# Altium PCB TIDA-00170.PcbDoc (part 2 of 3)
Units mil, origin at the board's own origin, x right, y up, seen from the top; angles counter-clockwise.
Board outline 3780 x 2000 mil, 4 copper layers (Top Layer, L2_GND-PLANE, L3_PWR-PLANE, Bottom Layer), stack 90 mil thick; 275 components, 132 nets, 768 pads, 262 vias.
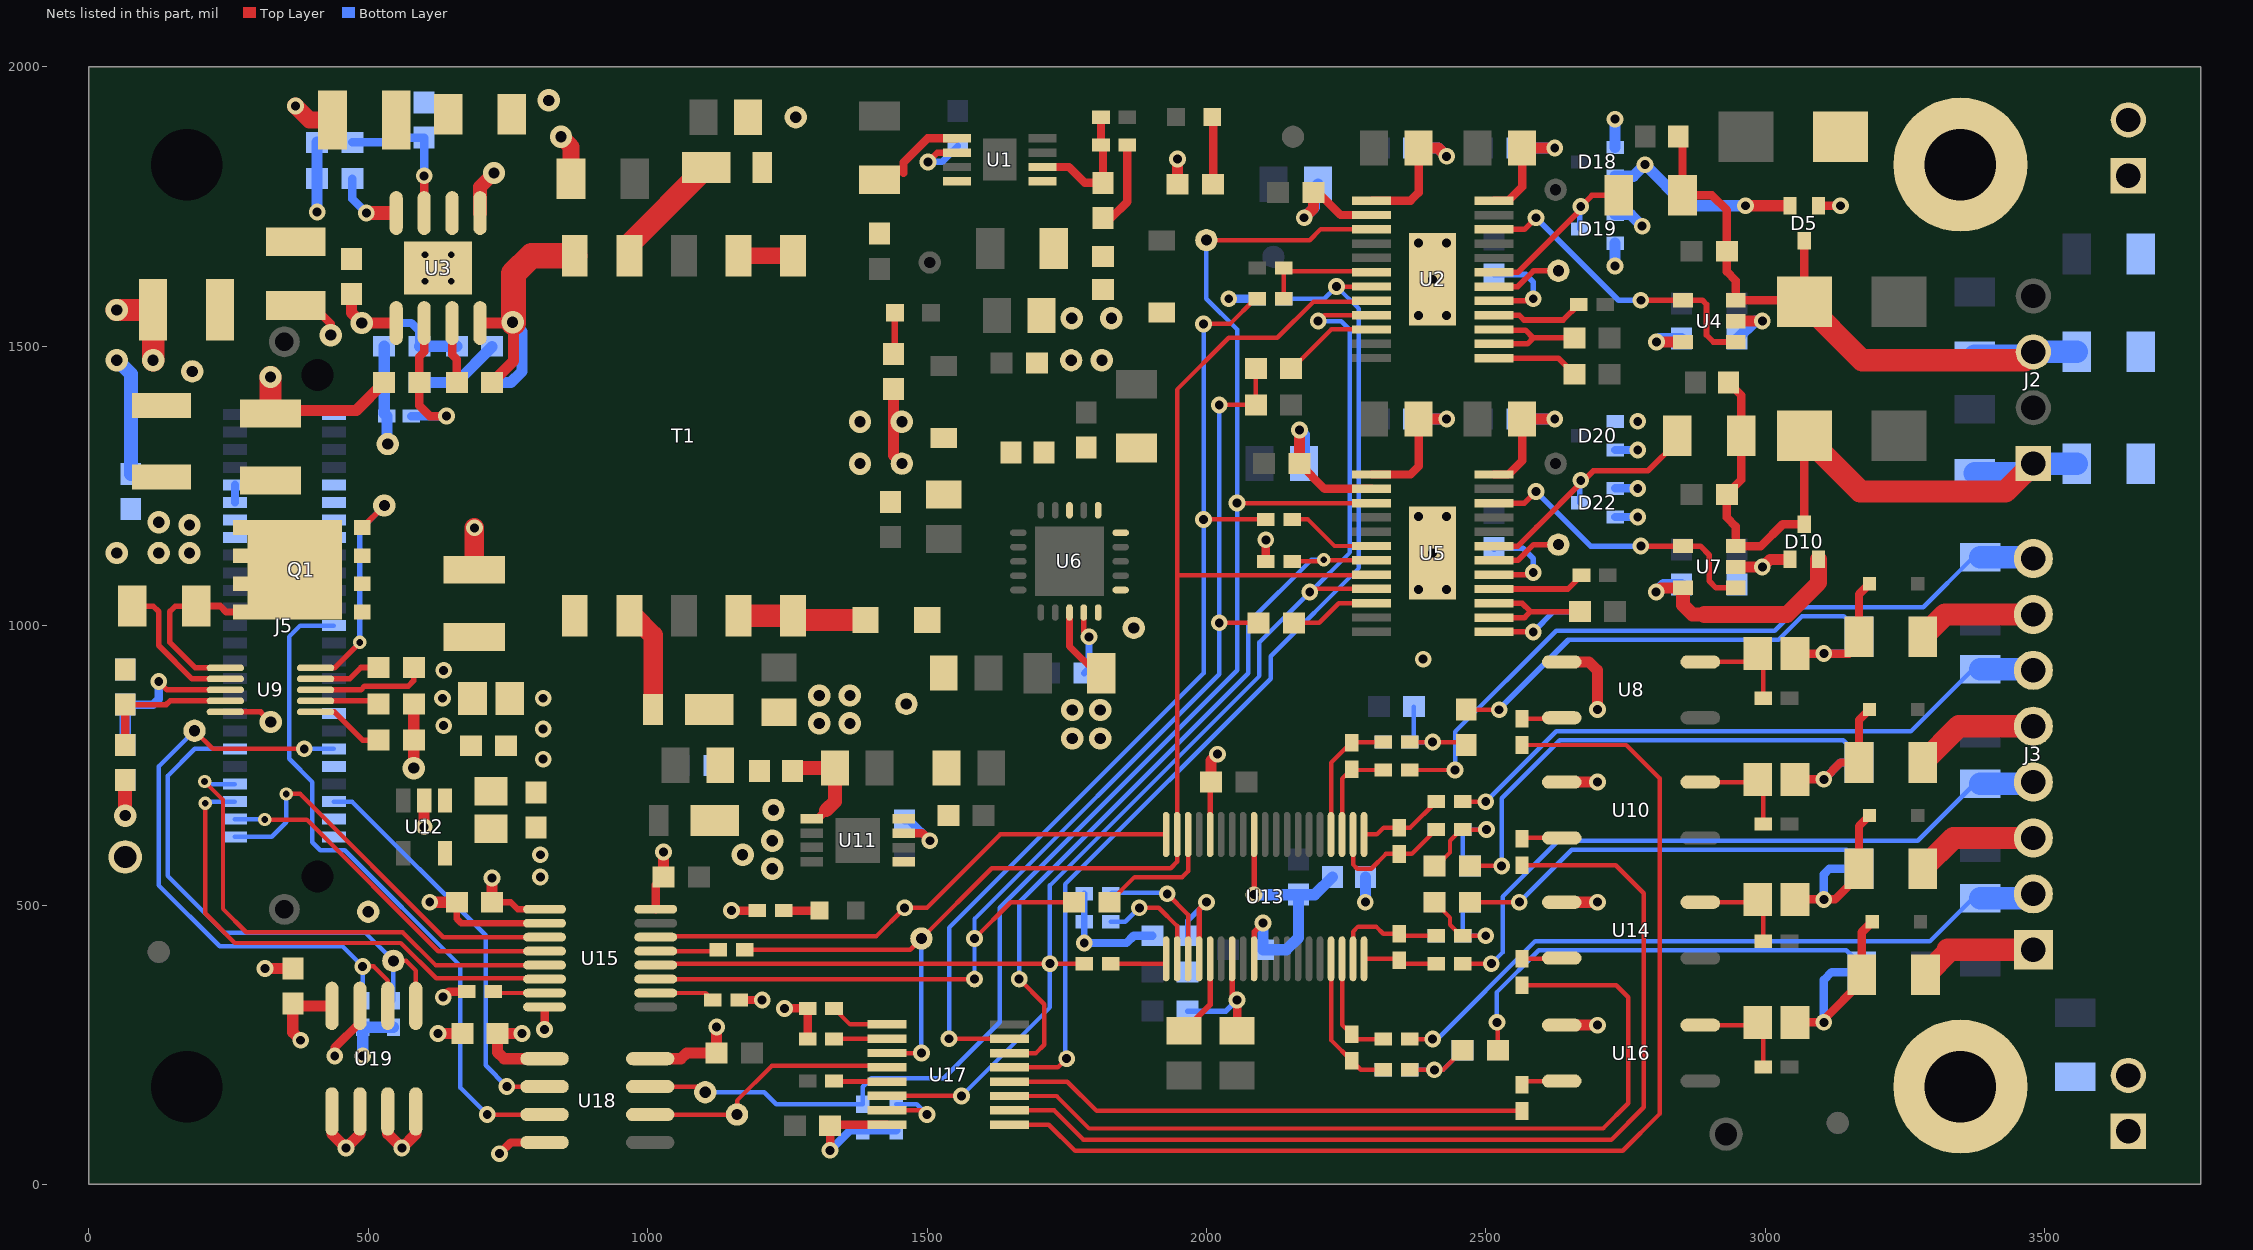
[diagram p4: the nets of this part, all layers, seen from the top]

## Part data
C1 C15 C22: "CAP, CERM, 2.2uF, 100V, +/-10%, X7R, 1210"
C2: "CAP, CERM, 0.47uF, 100V, +/-10%, X7R, 1206"
C3 C34 C35: "CAP, CERM, 2.2uF, 25V, +/-10%, X7R, 0805"
C4 C33: "CAP, CERM, 4.7uF, 50V, +/-10%, X7R, 1206"
C5 C6 C16 C23 C24 C28 C43 C66 C78: "CAP, CERM, 4.7uF, 50V, +/-10%, X5R, 0805"
C7 C67 C68 C71 C74 C77 C93: "CAP, CERM, 1000pF, 2KV 10% X7R 1206"
C8 C21 C63: "CAP, CERM, 0.01uF, 100V, +/-5%, X7R, 0603"
C9 C11 C14 C17 C18 C25 C27 C29 C30 C32 C40 C46 C47 C48 C51 C52 C55 C58 C60 C62 C64 C65 C69 C70 C75 C76 C80 C81: "CAP, CERM, 0.1uF, 50V, +/-10%, X7R, 0603"
C10 C26: "CAP, CERM, 3900pF, 50V, +/-10%, X7R, 0603"
C12 C19: "CAP, CERM, 10uF, 25V, +/-10%, X7R, 1206"
C13: "CAP, CERM, 10uF, 50V, +/-10%, X7R, 1210"
C20: "CAP, CERM, 1uF, 50V, +/-10%, X5R, 0603"
C31: "CAP, CERM, 10uF, 35V, +/-20%, X7R, 1210"
C36: "CAP, CERM, 1uF, 50V, +/-10%, X7R, 0805"
C37 C49 C54 C61: "CAP, CERM, 1000pF, 50V, +/-20%, X7R, 0402"
C38: "CAP, CERM, 0.47uF, 50V, 10%, X5R, 0603"
C39 C50 C53 C59: "CAP, CERM, 0.01uF, 50V, +/-10%, X7R, 0402"
C41 C42: "CAP, CERM, 22uF, 16V, +/-20%, X5R, 0805"
C44: "CAP, CERM, 10uF, 25V, +/-20%, X5R, 0603"
C45 C56: "CAP, CERM, 10uF, 16V, +/-20%, X5R, 0805"
C57: "CAP, CERM, 22uF, 16V, +/-10%, X5R, 0805"
C72: "CAP, CERM, 0.1uF, 100V, +/-10%, X7R, 0603"
C73: "CAP, CERM, 3300pF, 100V, +/-5%, X7R, 0603"
C79: "CAP, CERM, 1000pF, 100V, +/-20%, X7R, 0603"
C82 C85 C87 C92: "CAP, CERM, 0.027uF, 50V, +/-5%, C0G/NP0, 1206"
C83: "CAP, CERM, 1uF, 25V, +/-10%, X7R, 0603"
C84 C89 C90 C95: "CAP, CERM, 2700pF, 100V, +/-5%, X7R, 0603"
C86: "CAP, CERM, 1000pF, 100V, +/-5%, X7R, 0603"
C88 C91: "CAP, CERM, 10uF, 16V, +/-20%, X5R, 0603"
C94: "CAP, CERM, 1uF, 16V, +/-10%, X7R, 0603"
D1 D6 D16: "LED SmartLED Green 570NM"
D2 D7 D9: "TVS 18 VOLT 600 WATT BI-DIR SMB"
D3 D13: "Diode, Schottky, 200V, 1A, PowerDI123"
D4 D8: "Diode, Zener, 18V, 1W, SOD-123"
D5 D10 D18 D19 D20 D22: library part BAV99WT1G, "Diode, P-N, 70V, 0.2A, SOT-323"
D11 D14 D15 D17: library part CDSOD323-T15SC, "Diode, TVS, ARRAY, 19V, SOD323"
D12: "Diode, Schottky, 60V, 1A, SOD-123F"
D21: "Diode, Schottky, 45V, 0.1A, SOD-523"
D23: "DIODE ZENER 5.9V 1W PMDS"
FB1 FB2: library part MMZ1608Y102B, "FERRITE CHIP 1000 OHM 300MA 0603"
FB3 L1 L3 L4: library part MMZ1608B102C, "FERRITE CHIP 1000 OHM 300MA 0603"
FID1 FID2 FID3 FID4 FID5 FID6: library part Fiducial40_0
H1 H2: "Machine Screw, Round, #4-40 x 1/4, Nylon, Philips panhead"
J1 J4: "Terminal Block, 2x1, 2.54mm, TH"
J2: "Receptacle, 100mil, 4X1 TH"
J3: "Terminal Block, 8x1, 2.54 mm, TH"
J5: "Receptacle, 0.8mm, 25x2, SMT"
L2: library part IND_ELJEA_SERIES, "Inductor, Chip, ±10%"
LBL1: library part THT-14-423-10, "Thermal Transfer Printable Labels, 0.650\" W x 0.200\" H - 10,000 per roll"
Logo1: library part TI_Logo, "Texas Instrument Corporate Signature"
MH1 MH2: library part "MH 3_0.5MM", "Mountin hole, NPTH Drill 3.2mm"
Q1: "MOSFET, N-CH, 60V, 50A, SON 5x6mm"
R1: library part CRCW04029K31FKED, "RES, 9.42k ohm, 1%, 0.063W, 0402"
R2: "RES, 110k ohm, 1%, 0.063W, 0402"
R3 R13: "RES, 10 ohm, 5%, 0.25W, 1206"
R4 R9: "RES, 4.7k ohm, 5%, 0.1W, 0603"
R5: "RES, 27.0k ohm, 1%, 0.1W, 0603"
R6 R7 R8 R14 R15 R28 R33 R41 R42 R54: "RES, 0 ohm, 5%, 0.063W, 0402"
R10 R19 R38: "RES, 10.0 ohm, 1%, 0.1W, 0603"
R11 R18: "RES, 15k ohm, 1/10W 0.1% 0603"
R12 R25 R36 R39 R53: "RES, 1.00k ohm, 1%, 0.1W, 0603"
R16 R47 R48 R49 R51 R55 R60 R79 R80: "RES, 10k ohm, 5%, 0.063W, 0402"
R17: "RES, 0.02 ohm, 1%, 1W, 1206"
R20 R29 R35 R44: "RES 100 OHM .4W 1% 0204 MELF"
R21 R30 R37 R50: "RES, 200 ohm, 0.1%, 0.125W, 0805"
R22: "RES, 10k ohm, 5%, 0.1W, 0603"
R23: "RES, 95.3k ohm, 1%, 0.1W, 0603"
R24: "RES, 56.0k ohm, 0.1%, 0.1W, 0603"
R26 R34 R43 R56: "RES, 680 ohm, 5%, 0.063W, 0402"
R27: "RES, 7.15k ohm, 1%, 0.1W, 0603"
R31 R32 R46 R52: "RES, 1.10k ohm, 1%, 0.063W, 0402"
R40: "RES, 1.2k ohm, 5%, 0.063W, 0402"
R45: "RES, 49.9 ohm, 1%, 0.063W, 0402"
R57: "RES, 4.87k ohm, 1%, 0.1W, 0603"
R58: "RES, 60.4k ohm, 0.1%, 0.1W, 0603"
R59: "RES, 91.0k ohm, 1%, 0.1W, 0603"
R61: "RES, 189k ohm, 0.1%, 0.1W, 0603"
R62: "RES, 56.2k ohm, 0.1%, 0.1W, 0603"
R63 R64 R68 R70: "RES 0.0 OHM .5W JUMP 1206 SMD"
R65: "RES, 71.5k ohm, 1%, 0.1W, 0603"
R66: "RES, 14.3k ohm, 1%, 0.1W, 0603"
R67 R69 R74 R78: "RES, 10.0Meg ohm, 1%, 0.063W, 0402"
R71 R72: "RES, 47k ohm, 5%, 0.063W, 0402"
R73 R75: "RES, 47.0k ohm, 0.1%, 0.1W, 0603"
R76 R77: "RES, 1.5k ohm, 5%, 0.063W, 0402"
T1: library part 750313995, "Transformer, 50uH, SMT"
TP1 TP4 TP7 TP8 TP13 TP14 TP18 TP19 TP23 TP26 TP27 TP28: library part TP-040_RND, "Test Point 40mil pad 20mil drill"
TP2 TP3 TP5 TP6 TP9 TP10 TP11 TP12 TP15 TP16 TP17 TP20 TP21 TP22 TP24 TP25: "Test Point 40mil pad 20mil drill"
U1: "-36V, -200mA, Ultralow-Noise, Negative Linear Regulator"
U2 U5: "1-Channel, 16-Bit, Programmable Current/Voltage Output DAC for 4-20mA Current Loop Applications"
U3: "100V, 600mA Constant On-Time Synchronous Buck Regulator, DDA0008B"
U4 U7: "Precision, Low Noise, Rail-to-Rail Output, 36V Zero-Drift Operational Amplifier"
U6: "36-V, 1-A, 4.17-µVRMS, RF LDO Voltage Regulator, RGW0020A"
U8 U10 U14 U16: "PHOTORELAY MOSFET 1A 4-SOP"
U9: "Positive High Voltage Hot Swap / Inrush Current Controller with Power Limiting, 10-pin MSOP, Pb-Free"
U11: library part TPS7A16XXDGN, "IC, 60-V, 6-A IQ, 100-mA, LDO Voltage Regulator with Enable and Power-Good Functions"
U12: "IC REG LDO 3.3V 0.15A SOT23-5"
U13: "16 bit 400KSPS 8 Channel SAR ADC"
U15: "4242-VPK Small-Footprint and Low-Power Quad Channels Digital Isolators, DBQ0016A"
U17: "IC, 8-Bit Shift Registers With 3-State Output Registers"
U18: "Low-Power Bidirectional I2C Isolators, D0008A"
U19: "IC, EEPROM, 2KBIT, 1MHZ, SOIC-8"
ZZ1: library part AssemblyNoteLabel
ZZ2 ZZ3 ZZ4: library part AssemblyNote

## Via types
v1: diameter 30, hole 16, Top Layer to Bottom Layer, tented both sides, 197 vias
v2: diameter 40, hole 20, Top Layer to Bottom Layer, tented both sides, 46 vias
v3: diameter 20, hole 8, Top Layer to Bottom Layer, tented both sides, 9 vias
v4: diameter 24, hole 12, Top Layer to Bottom Layer, tented both sides, 6 vias
v5: diameter 25.98, hole 12, Top Layer to Bottom Layer, tented both sides, 4 vias

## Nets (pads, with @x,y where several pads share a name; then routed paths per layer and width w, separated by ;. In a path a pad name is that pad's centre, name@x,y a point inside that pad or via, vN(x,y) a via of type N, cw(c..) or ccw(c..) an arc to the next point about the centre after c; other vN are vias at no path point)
9.3V_NON_ISO: C31.1 C36.1 C40.1 C73.2 D21.2 R61.2 T1.10 TP8.1 U12.1 | length 177.7
  Bottom Layer w20: R61.2@528.5,1500 C73.2@528.5,1435 528.5,1379.84 D21.2@533.35,1375 533.35,1326.65 TP8.1@535,1325
  other v1: 635,821 633,870 635,920
+3.3V_NON_ISO: C45.1 C46.1 C52.2 C55.2 C58.2 R47.1 R76.1 R77.1 TP19.1 U12.5 U15.1 U18.1 U19.8 | length 604.6
  Top Layer w12: C52.2@721.5,505 755,505 767.5,492.5 U15.1@815.59,492.5
  Top Layer w15: v1(634,335) 644,345 R47.1@676.38,345
  Top Layer w20: v1(379,258) 365,272 C55.2@365,323.5 369.02,319.49 U19.8@435,319.49 ; C52.2@721.5,505 v1(721.5,548.5) ; v1(775.18,270) C58.2@731.5,270 731.5,236.5 743,225 U18.1@815.51,225
  Bottom Layer w20: v1(490,230) R77.1@490,281.38 R76.1@545,281.38
  other v1: 808,550 808,590
+5V_ISO: C9.2 C27.2 C43.1 C44.1 C48.2 C51.1 C60.1 C62.2 C66.2 C78.1 D23.1 FB3.1 L4.2 R16.2 R40.1 R48.2 R49.1 R51.1 R60.2 R71.1 R72.1 R73.1 R79.2 R80.2 TP16.1 U2.2 U5.2 U8.1 U10.1 U13.34 U14.1 U15.16 U16.1 U17.16 U18.8 | length 2083.8
  Top Layer w10: C44.1@1998.5,720 C44.1@2003.5,715 ; U13.34@2006.57,626.22 C44.1@2006.57,711.93
  Top Layer w15: U15.16@1014.41,492.5 1014.41,535.91 C51.1@1028.5,550 ; v1(1150,490) R40.1@1196.38,490 ; R48.2@1168.62,330 v1@1210,330 ; v1(1245,315) R49.1@1286.38,315 R51.1@1286.38,260 ; v1(1326.5,61) C62.2@1326.5,105 ; C62.2@1328.5,107 U17.16@1428.3,107 ; R16.2@2106.38,1115 v1(2106.38,1153.62) ; C27.2@2166.5,1290 2211.6,1244.9 U5.2@2295.7,1244.9 ; C9.2@2191.5,1775 2199.98,1775 2240.08,1734.9 U2.2@2295.7,1734.9
  Top Layer w20: U18.8@1004.49,225 1060,225 1070,235 C60.1@1123.5,235 v1(1123.5,281.5) ; C51.1@1028.5,550 v1(1028.5,595) ; C44.1@2008.5,720 2008.5,758.5 v1(2020,770) ; C27.2@2166.5,1290 v1(2166.5,1350) ; v1(2175,1730) 2191.5,1746.5 C9.2@2191.5,1775 ; U16.1@2635.98,285 v1(2700,285) ; U14.1@2635.98,505 v1(2700,505) ; U10.1@2635.98,720 v1(2700,720) ; U8.1@2635.98,935 2685,935 2700,920 v1(2700,850)
  Bottom Layer w12: v1(1781.38,432) R72.1@1781.38,470 R71.1@1781.38,520
  Bottom Layer w15: v1(1326.5,61) 1361.87,96.38 R80.2@1385,96.38 R79.2@1445,96.38 ; v1(1781.38,432) 1857,432 1870,445 R73.1@1903.5,445 ; v1(2040,1585) R60.2@2091.38,1585
  Bottom Layer w20: v1(2166.5,1350) 2175,1341.5 C78.1@2175,1290 ; v1(2175,1730) 2193.4,1748.4 2193.4,1783.4 C66.2@2200,1790 ; v1(2284.53,505) FB3.1@2284.53,550
  other v1: 1205,330
  other v2: 1223,565 1170,590 1223,615
+5V_ISO_AVDD: C88.1 C91.1 FB3.2 U13.9 U13.30 | length 529.3
  Top Layer w10: U13.9@2085.31,403.78 2085.31,451.82 v1(2101.5,468) ; v1(2085.32,518.5) U13.30@2085.31,626.22
  Bottom Layer w20: v1(2085.32,518.5) C88.1@2165,518.5 ; v1(2101.5,468) C91.1@2101.5,420 2143.58,420 2165,441.42 C88.1@2165,518.5 ; FB3.2@2225.47,550 2193.98,518.5 C88.1@2165,518.5
+6V_ISO: C35.1 C42.1 C47.2 D12.1 TP14.1 U11.5 U11.8
+15V_ISO: C6.2 C24.1 C28.1 C30.2 C64.1 C70.1 C76.2 C81.2 D5.2 D8.1 D10.2 D18.2 D19.2 D20.2 D22.2 L3.2 R9.1 TP10.1 U2.24 U4.5 U5.24 U7.5 | length 1668.5
  Top Layer w15: U5.24@2514.7,1270.5 2540.5,1270.5 2565,1295 C24.1@2565,1370 ; U2.24@2514.7,1760.5 2540.5,1760.5 2565,1785 C6.2@2565,1860
  Top Layer w20: R9.1@1440,1423.5 1440,1305 TP10.1@1455,1290 ; C6.2@2565,1855 v1(2623.5,1855) ; C24.1@2573.5,1370 v1(2623.5,1370) ; v1(2805,1060) 2812.6,1067.6 U7.5@2852.76,1067.6 ; v1(2805.4,1507.6) U4.5@2852.76,1507.6 ; v1(2965,1751.5) D5.2@3044.41,1751.5
  Top Layer w25: U7.5@2852.76,1067.6 2852.76,1037.24 2870,1020 2891.5,1020
  Top Layer w30: 2891.5,1020 3038.92,1020 3095.59,1076.67 D10.2@3095.59,1118.5
  Bottom Layer w15: D22.2@2731.5,1194.41 v1(2772,1194.41) ; D20.2@2731.5,1314.41 v1(2772,1314.41)
  Bottom Layer w20: C76.2@2556.5,1370 v1(2623.5,1370) ; C64.1@2556.5,1855 v1(2623.5,1855) ; v1(2731.5,1643.5) D19.2@2731.5,1684.41 ; D18.2@2731.5,1804.41 2764.41,1804.41 v1(2785,1825) 2858.5,1751.5 v1(2965,1751.5) ; v1(2805,1060) 2818.5,1073.5 C81.2@2850,1073.5 ; v1(2805.4,1507.6) 2811.31,1513.5 C70.1@2850,1513.5
  other v2: 1380,1290 1380,1365 1455,1365
+18V_ISO: C33.1 C34.1 D13.1 TP13.1 U6.13 U6.15 U6.16 | length 137.4
  Top Layer w12: U6.13@1755,1023.46 1755,963 1803,915 C33.1@1812.09,915
  other v2: 1760,798 1810,798 1307,825 1362,825 1760,849 1810,849 1307,875 1362,875
+24VDC: C79.1 J5.35 J5.36 J5.37 J5.38 R17.1 R23.2 R65.2 TP12.1 U9.2 | length 265.8
  Top Layer w10: R17.1@67.91,1035.32 R17.1@77.91,1035.32 ; R17.1@77.91,1035 115,1035 125,1025 125,964.54 184.86,904.69 U9.2@244.29,904.69
  other v2: 50,1130 180,1130 180,1180 125,1185
+24VDC_LIMIT: C22.1 L2.1 Q1.1 Q1.2 Q1.3 R22.2 U9.9 | length 121.2
  Top Layer w10: U9.9@405.71,904.69 466.69,904.69 487,925 R22.2@518.5,925
+VSEN0: U2.22 U4.1 U4.4 | length 565.5
  Top Layer w10: U2.22@2514.7,1709.2 2569.2,1709.2 v1(2590,1730) ; v1(2777.6,1582.4) U4.4@2852.76,1582.4 2887.6,1582.4 2895,1575 2895,1520 2907.4,1507.6 U4.1@2947.24,1507.6
  Bottom Layer w10: v1(2590,1730) 2737.6,1582.4 v1(2777.6,1582.4)
+VSEN1: U5.22 U7.1 U7.4 | length 539.8
  Top Layer w10: U5.22@2514.7,1219.2 2569.2,1219.2 v1(2590,1240) ; v1(2777.6,1142.4) U7.4@2852.76,1142.4 2884.09,1142.4 2900,1126.5 2900,1080 2912.4,1067.6 U7.1@2947.24,1067.6
  Bottom Layer w10: v1(2590,1240) 2687.6,1142.4 v1(2777.6,1142.4)
-15V_ISO: C5.1 C16.2 C18.2 C23.2 C65.2 C69.1 C75.1 C80.2 D4.2 D5.1 D10.1 D18.1 D19.1 D20.1 D22.1 L1.2 R4.1 R67.1 R69.1 R74.1 R78.1 TP6.1 U2.1 U2.25 U4.2 U5.1 U5.25 U7.2 | length 1016.5
  Top Layer w15: U5.1@2295.7,1270.5 2365.5,1270.5 2380,1285 C23.2@2380,1370 ; U2.1@2295.7,1760.5 2365.5,1760.5 2380,1775 C5.1@2380,1855 ; D5.1@3095.59,1751.5 v1(3135,1751.5)
  Top Layer w20: R4.1@1948.5,1790 v1(1948.5,1835) ; C23.2@2380,1370 v1(2430,1370) ; C5.1@2380,1855 2415,1855 v1(2430,1840) ; U7.2@2947.24,1105 v1(2995,1105) 3008.5,1118.5 D10.1@3044.41,1118.5 ; U4.2@2947.24,1545 v1(2995,1545)
  Bottom Layer w15: D22.1@2731.5,1245.59 v1(2772,1245.59)
  Bottom Layer w20: C75.1@2371.5,1370 v1(2430,1370) ; C65.2@2371.5,1855 2415,1855 v1(2430,1840) ; D19.1@2731.5,1735.59 2759.41,1735.59 v1(2780,1715) ; D18.1@2731.5,1855.59 v1(2731.5,1906.5) ; C69.1@2950,1513.5 2950.85,1513.5 2982.35,1545 v1(2995,1545)
  other v1: 2388,940 2380,1065 2430,1065 2405,1129.9 2380,1195 2430,1195 2772,1365.59 2380,1555 2430,1555 2405,1619.9 2380,1685 2430,1685
  other v2: 1813,1475 1759,1550 1830,1550
-18V_ISO: C3.2 C4.1 C11.2 D3.2 TP1.1 U1.5 U1.8 | length 132.3
  Top Layer w15: 1458,1810 1458,1829.13 1500.87,1872 U1.5@1553.4,1872
/ALARM: J5.6 U18.2 | length 724.7
  Top Layer w8: v1(748,175) U18.2@815.51,175
  Bottom Layer w8: J5.6@438.58,685.04 470.96,685.04 710,446 710,213 v1(748,175)
/ALARM_ISO: R80.1 TP3.1 TP26.1 U2.3 U5.3 U18.7 | length 2860.7
  Top Layer w8: U18.7@1004.49,175 1093,175 TP26.1@1103,165 ; TP3.1@2000,1690 2185,1690 2204.3,1709.3 U2.3@2295.7,1709.3 ; v1(2055,1219.3) U5.3@2295.7,1219.3
  Bottom Layer w8: TP26.1@1103,165 1208.62,165 1230,143.62 R80.1@1385,143.62 1385,175 1400,190 1530,190 1630,290 1630,495 2055,920 2055,1530 2000,1585 TP3.1@2000,1690
/CS0: J5.1 U15.3 | length 721.8
  Top Layer w8: v4(353,698.74) 378.08,698.74 634.32,442.5 U15.3@815.59,442.5
  Bottom Layer w8: J5.1@261.42,622.05 327.05,622.05 353,648 v4(353,698.74)
/CS0_ISO: TP18.1 U13.38 U15.14 | length 989.5
  Top Layer w8: U15.14@1014.41,442.5 1015.72,443.81 1408.81,443.81 TP18.1@1460,495 1500,495 1631.22,626.22 U13.38@1927.83,626.22
/CS1_ISO: R60.1 TP25.1 U2.7 U17.5 | length 1892.5
  Top Layer w8: U17.5@1647.3,209.4 1734.4,209.4 TP25.1@1750,225 ; v1(2233,1606.9) U2.7@2295.7,1606.9
  Bottom Layer w8: TP25.1@1750,225 1747.5,227.5 1747.5,537.5 2115,905 2115,945.25 2273,1103.25 2273,1566.9 v1(2233,1606.9) 2211.1,1585 R60.1@2138.62,1585
/CS2_ISO: R16.1 TP24.1 U5.7 U17.6 | length 1338
  Top Layer w8: U17.6@1647.3,235 1695,235 1710,250 1710,322.5 TP24.1@1665,367.5 ; R16.1@2153.62,1115 2207,1115 v4(2210,1118) 2211.1,1116.9 U5.7@2295.7,1116.9
  Bottom Layer w8: TP24.1@1665,367.5 1665,505 2075,915 2075,1005 2188,1118 v4(2210,1118)
\R\E\F\S\E\L\: R73.2 R75.1 U13.4 | length 245.5
  Top Layer w10: U13.4@1986.89,403.78 1986.89,491.89 v1(2000,505)
  Bottom Layer w10: R75.1@1966.5,380 R73.2@1966.5,445 1966.5,471.5 v1(2000,505)
\R\S\T\/\P\D\: R72.2 U13.2 | length 201.4
  Top Layer w8: v1(1880,495) 1915,495 1947.52,462.48 U13.2@1947.52,403.78
  Bottom Layer w8: R72.2@1828.62,470 1855,470 v1(1880,495)
AIN0: C95.1 R53.2 R54.1 R78.2 | length 221.5
  Top Layer w8: R54.1@2360.91,205 R54.1@2363.62,205 v1(2408,205) 2423.5,205 R53.2@2458.5,240
  Bottom Layer w8: R78.2@2363.62,205 v1(2408,205) 2423.5,205 C95.1@2458.5,240
AIN1: C90.1 R39.2 R41.1 R74.2 | length 230.4
  Top Layer w8: R39.2@2408.5,505 2436,477.5 2436,464.91 2455.91,445 R41.1@2458.62,445 v1(2500,445)
  Bottom Layer w8: C90.1@2471.5,505 2458.62,492.13 R74.2@2458.62,445 v1(2500,445)
AIN2: C89.1 R33.2 R36.2 R69.2 | length 243.4
  Top Layer w8: R36.2@2408.5,575 2417,575 2436,594 2436,615.09 2455.91,635 R33.2@2458.62,635 v1(2501.5,635)
  Bottom Layer w8: C89.1@2471.5,570 2458.62,582.87 R69.2@2458.62,635 v1(2501.5,635)
AIN3: C84.1 R25.2 R28.2 R67.2 | length 210.7
  Top Layer w8: R28.2@2363.62,791.65 v1(2405,791.65) 2461.85,791.65 R25.2@2465,788.5
  Bottom Layer w8: C84.1@2371.5,855 2371.5,799.53 R67.2@2363.62,791.65 v1(2405,791.65)
AOUT0: C14.1 C68.1 C71.1 D5.3 D7.1 FB1.1 J2.3 R3.1 U4.3 | length 1249.6
  Top Layer w15: FB1.1@2844.53,1875 2852.09,1867.44 R3.1@2852.09,1770 2905,1770 2931.5,1743.5 C14.1@2931.5,1670 2931.5,1633.5 2947.24,1617.76 U4.3@2947.24,1582.4 D7.1@3066.1,1582.4 ; D5.3@3066.1,1692.4 D5.3@3070,1688.5 D7.1@3070,1580.35
  Top Layer w40: D7.1@3066.1,1582.4 3173.5,1475 3465,1475 J2.3@3480,1490 ; D7.1@3070,1580.35 D7.1@3070.35,1580
  Bottom Layer w40: C68.1@3375,1482.91 3472.91,1482.91 J2.3@3480,1490 C71.1@3557.91,1490
AOUT1: C29.1 C74.1 C77.1 D9.1 D10.3 FB2.1 J2.1 R13.1 U7.3 | length 1284.6
  Top Layer w15: FB2.1@2934.53,1435 2957.09,1412.44 R13.1@2957.09,1340 2957.09,1260.59 C29.1@2931.5,1235 2931.5,1193.5 2947.24,1177.76 U7.3@2947.24,1142.4 2992.4,1142.4 3031.5,1181.5 D10.3@3070,1181.5 3070,1339.65 D9.1@3070.35,1340 ; D10.3@3070.35,1175.35 D10.3@3070.35,1181.5
  Top Layer w40: D9.1@3070.35,1340 3170.35,1240 3430,1240 J2.1@3480,1290
  Bottom Layer w40: C74.1@3375,1272.91 3462.91,1272.91 J2.1@3480,1290 C77.1@3557.91,1290
CLR: R7.1 R14.1 U17.7 | length 1802.4
  Top Layer w8: v1(1539.4,260.6) U17.7@1647.3,260.6 ; v1(1995,1190) R14.1@2106.38,1190 ; v1(1995,1540) 2042.37,1540 2087.37,1585 R7.1@2091.38,1585
  Bottom Layer w8: v1(1539.4,260.6) 1539.4,459.4 1995,915 v1(1995,1540)
DAISY: R71.2 U13.3 | length 234.7
  Top Layer w8: v1(1930,520) 1967.2,482.8 U13.3@1967.2,403.78
  Bottom Layer w8: R71.2@1828.62,520 1830.62,522 1928,522 v1(1930,520)
EVM_ID_SCL: J5.12 R77.2 TP15.1 U19.6 | length 1153.7
  Top Layer w8: TP15.1@189,812 221.47,779.53 v1(385.47,779.53) ; v1(490,390) 509.75,390 535,364.75 U19.6@535,319.49
  Bottom Layer w8: TP15.1@189,812 125,748 125,535 234,426 454,426 v1(490,390) R77.2@490,328.62 ; v1(385.47,779.53) J5.12@438.58,779.53
EVM_ID_SDA: J5.11 R76.2 TP21.1 U19.5 | length 968.2
  Top Layer w8: TP21.1@545,400 567.63,400 585,382.63 U19.5@585,319.49
  Bottom Layer w8: J5.11@261.42,779.53 189.53,779.53 141,731 141,552 243,450 495,450 TP21.1@545,400 R76.2@545,328.62
GND: C1.1 C2.1 C7.1 C13.2 C15.1 C20.2 C22.2 C31.2 C36.2 C38.2 C40.2 C45.2 C46.2 C52.1 C55.1 C58.1 C79.2 J5.2 J5.4 J5.10 J5.16 J5.39 J5.40 J5.41 J5.42 J5.50 R5.1 R24.1 R27.1 R57.1 R66.1 TP17.1 U3.1 U3.9 U9.5 U12.2 U15.2 U15.8 U18.4 U19.1 U19.2 U19.3 U19.4 U19.7 | length 2323
  Top Layer w10: U9.5@244.29,845.63 307.41,845.63 v2(325.52,827.52)
  Top Layer w12: C52.1@658.5,505 658.5,475.3 666.3,467.5 U15.2@815.59,467.5
  Top Layer w15: C13.2@370,1572.91 400.09,1572.91 433,1540 v2(433,1520) ; v1(440,230) 440,245 U19.7@485,290 ; v1(735,55) 755,75 U18.4@815.51,75 ; v1(815.59,277.41) U15.8@815.59,317.5
  Top Layer w20: v1(315,386.5) C55.1@365,386.5 ; C22.2@325,1385 478.5,1385 C20.2@528.5,1435 ; U19.1@435,130.51 435,90 v1(460,65) 485,90 U19.2@485,130.51 ; U19.3@535,130.51 535,90 v1(560,65) 585,90 U19.4@585,130.51 ; v2(581.5,745) C38.2@581.5,795 R24.1@581.5,860 ; v1(600,640) U12.2@600,687.24 ; v1(610,505) C52.1@658.5,505 ; v1(624.82,270) C58.1@668.5,270
  Top Layer w25: v2(65,660) R27.1@65,723.5 ; U3.1@700,1738.43 700,1785 v2(725,1810)
  Top Layer w30: v1(370,1930) 395,1905 C1.1@435.91,1905 ; v2(845,1875) 862.91,1857.09 C7.1@862.91,1800
  Top Layer w35: C31.2@690,1100 v1(690,1175)
  Top Layer w40: v2(50,1565) C15.1@115,1565 v2(115,1475) ; C22.2@325,1380 v2(325,1445)
  Bottom Layer w15: J5.39@261.42,1220.47 J5.41@261.42,1251.97
  Bottom Layer w25: v2(50,1475) 75,1450 C79.2@75,1271.5 ; v2(65,660) R66.1@65,723.5
  other v1: 813,761 813,815 813,870
  other v2: 823,1940
  other v5: 601.38,1616.38 648.62,1616.38 601.38,1663.62 648.62,1663.62
GND_EARTH: C67.2 C71.2 C77.2 C93.2 D2.2 H1.1 H2.1 J1.1 J1.2 J4.1 J4.2
HART0: TP5.1 U2.18 | length 127
  Top Layer w10: U2.18@2514.7,1606.8 2557.26,1606.8 2585.46,1635 TP5.1@2630,1635
HART1: TP11.1 U5.18 | length 127
  Top Layer w10: U5.18@2514.7,1116.8 2557.26,1116.8 2585.46,1145 TP11.1@2630,1145
IN_AIN0: J3.1 R44.1 | length 216.6
  Top Layer w40: R44.1@3287.09,375 3332.09,420 ; 3327.09,420 3332.09,420 ; J3.1@3480,420 3332.09,420
IN_AIN0_N: J3.2 R52.1 R70.2 | length 1224.1
  Top Layer w8: R52.1@2363.62,260 v1(2405,260)
  Bottom Layer w8: v1(2405,260) 2413.18,260 2588.18,435 3295,435 3372.09,512.09 R70.2@3385,512.09
  Bottom Layer w40: R70.2@3385,512.09 3472.09,512.09 J3.2@3480,520
IN_AIN1: J3.3 R35.1 | length 220.7
  Top Layer w40: R35.1@3282.09,565 3337.09,620 J3.3@3480,620
IN_AIN1_N: J3.4 R46.1 R68.2 | length 1214.6
  Top Layer w8: R46.1@2458.62,395 v1(2510,395)
  Bottom Layer w8: v1(2510,395) 2530,415 2530,515 2630,615 3273.18,615 3375.27,717.09 R68.2@3385,717.09
  Bottom Layer w40: R68.2@3385,717.09 3477.09,717.09 J3.4@3480,720
IN_AIN2: J3.5 R29.1 | length 224.8
  Top Layer w40: R29.1@3282.09,755 3347.09,820 J3.5@3480,820
IN_AIN2_N: J3.6 R32.2 R64.2 | length 1117.5
  Top Layer w8: R32.2@2458.62,685 v1(2500,685)
  Bottom Layer w8: v1(2500,685) 2626,811 3261,811 3372.09,922.09 R64.2@3385,922.09
  Bottom Layer w40: R64.2@3385,922.09 J3.6@3477.91,922.09
IN_AIN3: J3.7 R20.1 | length 214.5
  Top Layer w40: R20.1@3282.09,980 3322.09,1020 J3.7@3480,1020
IN_AIN3_N: J3.8 R31.2 R63.2 | length 1314.9
  Top Layer w8: R31.2@2363.62,741.65 v1(2445,741.65)
  Bottom Layer w8: v1(2445,741.65) 2445,810 2626,991 3017.37,991 3059.37,1033 3283,1033 3372.09,1122.09 R63.2@3385,1122.09
  Bottom Layer w40: R63.2@3385,1122.09 3477.91,1122.09 J3.8@3480,1120
IOUT0: D19.3 R3.2 U2.19 | length 333.8
  Top Layer w10: U2.19@2514.7,1632.4 2557.4,1632.4 2590.6,1665.6 2590.65,1665.6 2670,1744.95 v1(2670,1750) 2690,1770 R3.2@2737.91,1770 ; R3.2@2752.91,1762.91 R3.2@2752.91,1775
  Bottom Layer w10: D19.3@2668.5,1710 v1@2668.5,1748.5
IOUT1: D22.3 R13.2 U5.19 | length 456
  Top Layer w10: U5.19@2514.7,1142.4 2557.4,1142.4 2590.6,1175.6 2590.65,1175.6 v1@2672.53,1257.47 ; v1(2670,1260) 2675.46,1260 2692.73,1277.27 2790.42,1277.27 2842.91,1329.76 R13.2@2842.91,1340
  Bottom Layer w10: D22.3@2668.5,1220 v1@2668.5,1258.5
MISO: J5.5 U15.6 | length 906.1
  Top Layer w8: v4(208,682) 208,485 261,432 558.25,432 621.44,368.81 U15.6@814.28,368.81
  Bottom Layer w8: v4(208,682) 211.04,685.04 J5.5@261.42,685.04
MISO_ISO: R10.1 R12.2 R19.1 R38.2 TP23.1 U15.11 | length 2183
  Top Layer w8: U15.11@1014.41,367.5 TP23.1@1585,367.5 ; v1(1585,440) 1650,505 R38.2@1763.5,505 ; v1(2023,1005) R19.1@2093.5,1005 ; v1(2023,1395) R12.2@2088.5,1395 R10.1@2088.5,1460
  Bottom Layer w8: TP23.1@1585,367.5 v1(1585,440) 1585,475 2023,913 v1(2023,1005) v1@2023,1392
MOSI: J5.7 U15.5 | length 915.2
  Top Layer w8: v4(207,721) 240,688 240,493 281.5,451.5 561.38,451.5 620.38,392.5 U15.5@815.59,392.5
  Bottom Layer w8: v4(207,721) 211.46,716.54 J5.7@261.42,716.54
MOSI_ISO: R45.1 TP22.1 U2.9 U5.9 U15.12 U17.14 | length 2837.7
  Top Layer w8: U15.12@1014.41,392.5 1016.91,395 TP22.1@1720,395 R45.1@1781.38,395 ; U17.14@1428.3,158.3 v1(1561.7,158.3) ; v1(2185,1060) 2190.7,1065.7 U5.9@2295.7,1065.7 ; v1(2200,1545) 2210.7,1555.7 U2.9@2295.7,1555.7
  Bottom Layer w8: v1(1561.7,158.3) 1720,316.6 TP22.1@1720,395 1720,535 2095,910 2095,970 v1(2185,1060) 2185.94,1060 2257,1131.06 2257,1529.4 2241.4,1545 v1(2200,1545)
NetC1_2: C1.2 C2.2 C13.1 C15.2 L2.2 R58.2 R59.2 TP7.1 U3.2 | length 124.5
  Bottom Layer w20: v1(408.5,1740.5) R59.2@408.5,1800 R58.2@408.5,1865
NetC8_1: C8.1 C12.1 L1.1 R2.1 U1.1 | length 162.1
  Top Layer w15: C8.1@1810,1729.5 C8.1@1815,1729.5 1829.5,1729.5 1858.62,1758.62 R2.1@1858.62,1860
NetC8_2: C8.2 R1.1 R2.2 U1.2 | length 238.7
  Top Layer w15: U1.2@1707,1820.8 1754.2,1820.8 1782.5,1792.5 C8.2@1815,1792.5 1815,1856.38 R2.2@1811.38,1860 R1.1@1811.38,1910
NetC10_2: C10.2 U2.17 | length 177.5
  Top Layer w10: U2.17@2514.7,1581.2 2581.2,1581.2 v1(2585,1585)
  Bottom Layer w10: C10.2@2515,1628.5 2571.5,1628.5 2585,1615 v1(2585,1585)
NetC17_2: C17.2 U2.14 U2.15 | length 224.7
  Top Layer w10: U2.14@2514.7,1504.4 2574.4,1504.4 2585,1515 ; U2.15@2514.7,1530 2515.7,1529 2571,1529 2585,1515 ; C17.2@2658.5,1515 2585,1515
NetC19_1: C19.1 C25.2 L3.1 U6.1 U6.3 U6.20
NetC20_1: C20.1 D21.1 U3.6 | length 271.1
  Top Layer w15: U3.6@600,1541.57 600,1490 591.5,1481.5 C20.1@591.5,1435 591.5,1393.5 610,1375 v1(640,1375)
  Bottom Layer w15: D21.1@576.65,1375 v1(640,1375)
NetC21_1: C21.1 U3.7 | length 110.1
  Top Layer w15: U3.7@650,1541.57 650,1485 658.5,1476.5 C21.1@658.5,1435
NetC21_2: C21.2 R62.2 T1.1 U3.8 | length 550.6
  Top Layer w20: U3.8@700,1541.57 760,1541.57 760,1473.5 C21.2@721.5,1435
  Top Layer w45: v2@760,1541.57 760,1630 792.05,1662.05 T1.1@869.72,1662.05
  Bottom Layer w20: R62.2@721.5,1435 755,1435 775,1455 775,1526.43 v2(758.43,1543)
NetC26_2: C26.2 U5.17 | length 174.8
  Top Layer w10: U5.17@2514.7,1091.2 2581.2,1091.2 v1(2585,1095)
  Bottom Layer w10: C26.2@2514.7,1136.5 C26.2@2515,1136.5 ; C26.2@2515,1138.5 2566.5,1138.5 2585,1120 v1(2585,1095)
NetC32_2: C32.2 U5.14 U5.15 | length 229.7
  Top Layer w10: U5.14@2514.7,1014.4 2569.4,1014.4 2580,1025 ; U5.15@2514.7,1040 2565,1040 2580,1025 ; C32.2@2668.5,1025 2580,1025
NetC37_1: C37.1 R21.1 U8.4 | length 192.8
  Top Layer w8: U8.4@2884.02,935 2971.54,935 R21.1@2986.54,950 2996.38,940.16 C37.1@2996.38,870
NetC38_1: C38.1 U9.6 | length 133.8
  Top Layer w10: U9.6@405.71,845.63 439.37,845.63 490,795 C38.1@518.5,795
NetC39_1: C39.1 R28.1 U13.23 | length 237.1
  Top Layer w8: U13.23@2223.11,626.22 2223.11,754.76 2260,791.65 R28.1@2316.38,791.65
NetC39_2: C39.2 R31.1 U13.22 | length 184.9
  Top Layer w8: U13.22@2242.8,626.22 2242.8,725.83 2258.62,741.65 R31.1@2316.38,741.65 ; R31.1@2312.76,743.03 R31.1@2316.38,746.65
NetC41_1: C41.1 L4.1 U11.1 | length 191.8
  Top Layer w15: U11.1@1293.5,654.2 1304.2,654.2 1319.6,669.6
  Top Layer w25: L4.1@1259.53,740 1264.53,745 C41.1@1335,745 1335,685 1319.6,669.6
NetC49_1: C49.1 R30.1 U10.4 | length 188.7
  Top Layer w8: U10.4@2884.02,720 2981.54,720 R30.1@2986.54,725 2996.38,715.16 C49.1@2996.38,645
NetC50_1: C50.1 R33.1 U13.21 | length 234.7
  Top Layer w8: U13.21@2262.48,626.22 2262.48,572.52 2270,565 2295,565 2321.38,591.38 C50.1@2345,591.38 2367.76,591.38 R33.1@2411.38,635
NetC50_2: C50.2 R32.1 U13.20 | length 153.6
  Top Layer w8: U13.20@2282.17,626.22 2305,626.22 2317.4,638.62 C50.2@2345,638.62 2365,638.62 R32.1@2411.38,685
NetC53_1: C53.1 R41.2 U13.18 | length 208
  Top Layer w8: U13.18@2262.48,403.78 2262.48,452.36 2271.5,461.38 2303.62,461.38 2316.38,448.62 C53.1@2345,448.62 2348.62,445 R41.2@2411.38,445
NetC53_2: C53.2 R46.2 U13.19 | length 136.5
  Top Layer w8: U13.19@2282.17,400.16 U13.19@2284.76,402.76 ; U13.19@2282.17,403.78 2343.98,403.78 2352.76,395 R46.2@2411.38,395
NetC54_1: C54.1 R37.1 U14.4 | length 183.7
  Top Layer w8: U14.4@2884.02,505 2981.54,505 R37.1@2986.54,510 2996.38,500.16 C54.1@2996.38,435
NetC56_1: C56.1 U13.5 | length 148.1
  Top Layer w10: C56.1@1960,275 2006.57,321.57 U13.5@2006.57,403.78
NetC57_2: C57.2 C94.2 U13.7 | length 229.3
  Top Layer w10: U13.7@2045.94,403.78 2045.94,339.06 v1(2055,330)
  Top Layer w15: C57.2@2055,275 v1(2055,330)
  Bottom Layer w10: C94.2@1966.5,310 2035,310 v1(2055,330)
NetC59_1: C59.1 R54.2 U13.16 | length 260.8
  Top Layer w8: U13.16@2223.11,403.78 2223.11,258.27 C59.1@2260,221.38 2276.38,205 R54.2@2316.38,205
NetC59_2: C59.2 R52.2 U13.17 | length 202.2
  Top Layer w8: U13.17@2242.8,403.78 2242.8,285.83 C59.2@2260,268.62 2268.62,260 R52.2@2316.38,260
NetC61_1: C61.1 R50.1 U16.4 | length 188.7
  Top Layer w8: U16.4@2884.02,285 2981.54,285 R50.1@2986.54,290 2996.38,280.16 C61.1@2996.38,210
NetC63_1: C63.1 U1.6 | length 123
  Top Layer w12: v1(1502,1830) 1518.4,1846.4 U1.6@1553.4,1846.4
  Bottom Layer w12: v1(1502,1830) 1526.5,1830 C63.1@1555,1858.5
NetC72_1: C72.1 C73.1 R62.1 | length 156.1
  Bottom Layer w20: C73.1@591.5,1435 R62.1@658.5,1435 ; R62.1@658.5,1436.16 C72.1@721.5,1499.15
NetC72_2: C72.2 R5.2 R61.1 U3.5 | length 324.4
  Top Layer w20: R5.2@470,1593.5 470,1560 v2(488.43,1541.57) ; v2(488.43,1541.57) U3.5@550,1541.57
  Bottom Layer w15: v2(488.43,1541.57) 577.19,1541.57 591.5,1527.27 R61.1@591.5,1500
  Bottom Layer w20: R61.1@591.5,1500 C72.2@658.5,1500
NetC82_1: C82.1 D11.1 R20.2 R21.2 R25.1 | length 1286.1
  Top Layer w8: R25.1@2465,849.5 v1(2524,849.5)
  Top Layer w15: R21.2@3053.46,950 v1(3105,950) 3150,950 3167.91,967.91 R20.2@3167.91,980 3167.91,1056.22 D11.1@3186.69,1075
  Bottom Layer w8: v1@2523.5,851.5 2647.01,975 ; v1(2524,849.5) 2649.5,975 3024,975 3066,1017 3141,1017 3167.91,990.09 C82.1@3167.91,980
  Bottom Layer w15: v1(3105,950) 3147.91,950 3167.91,970 C82.1@3167.91,980
NetC83_1: C83.1 U6.14 | length 115.9
  Top Layer w10: U6.14@1780.59,1023.46 1780.59,989.41 v1(1790,980)
  Bottom Layer w12: C83.1@1781.5,915 1790,923.5 v1(1790,980)
NetC85_1: C85.1 D14.1 R29.2 R30.2 R36.1 | length 1177
  Top Layer w8: R36.1@2471.5,570 v1(2528.5,570)
  Top Layer w15: R30.2@3053.46,725 v1(3105,725) 3135,755 R29.2@3167.91,755 3167.91,831.22 D14.1@3186.69,850
  Bottom Layer w8: v1(2528.5,570) 2528.5,690.87 2632.63,795 3140,795 C85.1@3167.91,767.09
  Bottom Layer w15: v1(3105,725) 3135,755 C85.1@3167.91,755
NetC86_1: C86.1 U11.7 | length 112.2
  Top Layer w15: U11.7@1458.5,628.5 1491.5,628.5 v1(1505,615)
  Bottom Layer w15: C86.1@1460,651.5 1468.5,651.5 v1(1505,615)
NetC87_1: C87.1 D15.1 R35.2 R37.2 R39.1 | length 1115.7
  Top Layer w8: R39.1@2471.5,505 v1(2560,505)
  Top Layer w15: R37.2@3053.46,510 v1(3105,510) 3125,510 3167.91,552.91 R35.2@3167.91,565 3167.91,641.22 D15.1@3186.69,660
  Bottom Layer w8: v1(2560,505) 2654,599 3146,599 3167.91,577.09 C87.1@3167.91,565
  Bottom Layer w15: v1(3105,510) 3105,555 3115,565 C87.1@3167.91,565
NetC92_1: C92.1 D17.1 R44.2 R50.2 R53.1 | length 1226.4
  Top Layer w8: R53.1@2521.5,240 v1@2521.5,288.5
  Top Layer w15: R50.2@3053.46,290 v1(3105,290) 3105,295 3172.91,362.91 R44.2@3172.91,375 3172.91,451.22 D17.1@3191.69,470
  Bottom Layer w8: v1(2520,290) 2520,344.19 2594.81,419 3145,419 3172.91,391.09 C92.1@3172.91,380
  Bottom Layer w15: v1(3105,290) 3105,366 3119,380 C92.1@3172.91,380
NetD1_1: D1.1 R4.2 | length 119
  Top Layer w15: R4.2@2012.48,1790.98 D1.1@2012.48,1910
NetD3_1: D3.1 T1.2 | length 214.9
  Top Layer w40: T1.2@967.36,1662.05 967.36,1682.56 D3.1@1104.8,1820
NetD6_2: D6.2 R9.2 | length 74.5
  Top Layer w12: R9.2@1440,1486.5 1442.52,1489.02 D6.2@1442.52,1560
NetD12_2: D12.2 T1.6 T1.7 | length 230.5
  Top Layer w40: T1.7@1162.64,1017.95 T1.6@1260.28,1017.95 1268.23,1010 D12.2@1389.88,1010
NetD13_2: D13.2 T1.9 | length 189.6
  Top Layer w35: T1.9@967.36,1017.95 974.28,1017.95 1009.8,982.43 D13.2@1009.8,850
NetD16_2: D16.2 R40.2 | length 63.9
  Top Layer w15: R40.2@1243.62,490 D16.2@1307.52,490
NetQ1_4: Q1.4 U9.10 | length 417.2
  Top Layer w10: U9.10@405.71,924.37 439.37,924.37 v4(485,970) ; Q1.4@489.3,1175.49 v2(528.81,1215)
  Bottom Layer w10: v4(485,970) 485,1171.19 v2(528.81,1215)
NetQ1_5: Q1.5 Q1.6 Q1.7 Q1.8 Q1.9 R17.2 U9.1 | length 325.5
  Top Layer w10: R17.2@192.09,1035 154.68,1035 145,1025.32 145,970 190.63,924.37 U9.1@244.29,924.37
  Top Layer w11: R17.2@192.09,1022.09 R17.2@192.09,1035
  Top Layer w12: R17.2@192.09,1035 235,1035 245.49,1024.51 Q1.8@275.7,1024.51
NetR6_1: R6.1 R7.2 U2.6 | length 215.2
  Top Layer w8: R7.2@2138.62,1585 R6.1@2138.62,1640 2144.72,1633.9 2294.3,1633.9 U2.6@2295.7,1632.5
NetR8_1: R8.1 U2.16 | length 166.8
  Top Layer w10: U2.16@2514.7,1555.6 2559.8,1555.6 2568.4,1547 2638.38,1547 R8.1@2666.38,1575
NetR10_2: R10.2 U2.10 | length 173.2
  Top Layer w8: R10.2@2151.5,1460 2153.18,1460 2223.28,1530.1 U2.10@2295.7,1530.1
NetR11_1: R11.1 U2.13 | length 155.7
  Top Layer w10: U2.13@2514.7,1478.8 2629.7,1478.8 R11.1@2658.5,1450
NetR14_2: R14.2 U5.6 | length 161.8
  Top Layer w8: R14.2@2153.62,1190 2181.82,1190 2229.32,1142.5 U5.6@2295.7,1142.5
NetR15_1: R15.1 U5.16 | length 166.8
  Top Layer w10: U5.16@2514.7,1065.6 2646.98,1065.6 R15.1@2671.38,1090
NetR18_1: R18.1 U5.13 | length 168.8
  Top Layer w10: U5.13@2514.7,988.8 v1(2585,988.8)
  Bottom Layer w10: v1(2585,988.8) 2621.2,1025 R18.1@2668.5,1025
NetR19_2: R19.2 U5.10 | length 160.8
  Top Layer w8: R19.2@2146.5,1005 R19.2@2151.5,1010 ; R19.2@2156.5,1005 2202.02,1005 2237.12,1040.1 U5.10@2295.7,1040.1
NetR22_1: R22.1 U9.8 | length 206.1
  Top Layer w10: U9.8@405.71,885 486.73,885 493.43,891.7 571.7,891.7 581.5,901.5 R22.1@581.5,925
NetR23_1: R23.1 R27.2 U9.4 | length 254.1
  Top Layer w10: R23.1@65,858.5 138.5,858.5 145.32,865.32 U9.4@244.29,865.32
  Top Layer w15: R27.2@65,786.5 R23.1@65,858.5
NetR24_2: R24.2 U9.7 | length 115
  Top Layer w10: U9.7@405.71,865.32 513.19,865.32 R24.2@518.5,860
NetR26_2: R26.2 U8.2 | length 71.4
  Top Layer w8: R26.2@2565,833.62 2634.61,833.62 U8.2@2635.87,834.89
NetR34_2: R34.2 U10.2 | length 71.6
  Top Layer w8: R34.2@2565,618.62 2566.38,620 U10.2@2635.98,620
NetR38_1: R38.1 U13.36 | length 229.3
  Top Layer w8: R38.1@1826.5,505 1871.5,550 1956.55,550 1967.2,560.65 U13.36@1967.2,626.22
NetR42_1: R42.1 U15.13 | length 109.5
  Top Layer w8: U15.13@1014.41,417.5 R42.1@1123.88,417.5
NetR43_2: R43.2 U14.2 | length 69.6
  Top Layer w8: R43.2@2565,403.62 U14.2@2634.61,403.62
NetR45_2: R45.2 U13.1 | length 108
  Top Layer w8: R45.2@1828.62,395 1927.83,395 U13.1@1927.83,403.78
NetR47_2: R47.2 U15.7 | length 93
  Top Layer w8: R47.2@723.62,345 726.12,342.5 U15.7@815.59,342.5
NetR48_1: R48.1 U15.10 | length 107.1
  Top Layer w8: U15.10@1014.41,342.5 1103.88,342.5 R48.1@1116.38,330
NetR49_2: R49.2 U17.9 | length 106.6
  Top Layer w8: R49.2@1333.62,315 1362.32,286.3 U17.9@1428.3,286.3
NetR51_2: R51.2 U17.10 | length 95
  Top Layer w8: R51.2@1333.62,260 1334.32,260.7 U17.10@1428.3,260.7
NetR55_2: R55.2 U17.13 | length 183.7
  Top Layer w8: R55.2@1333.62,185 1427.2,185 U17.13@1428.3,183.9 R55.2@1339.72,183.9
NetR56_2: R56.2 U16.2 | length 82.4
  Top Layer w8: R56.2@2565,173.62 2565,185 U16.2@2635.98,185
NetR57_2: R57.2 R58.1 U3.3 | length 267.1
  Top Layer w15: U3.3@600,1738.43 v1(600,1805)
  Bottom Layer w15: R58.1@471.5,1865 526.5,1865 535,1873.5 R57.2@600,1873.5 v1(600,1805)
NetR59_1: R59.1 U3.4 | length 125.4
  Top Layer w25: v1(496.57,1738.43) U3.4@550,1738.43
  Bottom Layer w15: R59.1@471.5,1800 471.5,1763.5 v1(496.57,1738.43)
NetR65_1: R65.1 R66.2 U9.3 | length 293.2
  Top Layer w10: v1(125,900) 140,885 U9.3@244.29,885
  Bottom Layer w15: R65.1@65,858.5 115,858.5 125,868.5 v1(125,900)
  Bottom Layer w20: R66.2@65,786.5 R65.1@65,858.5
NetR79_1: R79.1 U17.15 | length 137.6
  Top Layer w8: U17.15@1428.3,132.7 1492.3,132.7 v1(1500,125)
  Bottom Layer w8: R79.1@1445,143.62 1481.38,143.62 v1(1500,125)
NetT1_4: T1.4 T1.5 | length 97.6
  Top Layer w30: T1.4@1162.64,1662.05 T1.5@1260.28,1662.05
OPTO_AN0: R56.1 U17.4 | length 939.4
  Top Layer w8: U17.4@1647.3,183.8 1751.2,183.8 1803.62,131.38 R56.1@2565,131.38
OPTO_AN1: R43.1 U17.3 | length 1539.3
  Top Layer w8: U17.3@1647.3,158.2 1731.8,158.2 1790,100 2710,100 2755,145 2755,335 2733.62,356.38 R43.1@2565,356.38
OPTO_AN2: R34.1 U17.2 | length 1803.4
  Top Layer w8: U17.2@1647.3,132.6 1727.4,132.6 1780,80 2725,80 2783,138 2783,521 2732.62,571.38 R34.1@2565,571.38
OPTO_AN3: R26.1 U17.1 | length 2082.1
  Top Layer w8: U17.1@1647.3,107 1718,107 1765,60 2745,60 2811,126 2811,727 2751.62,786.38 R26.1@2565,786.38
RCLK: J5.26 U18.3 | length 1218.7
  Top Layer w8: v1(713,125) U18.3@815.51,125
  Bottom Layer w8: J5.26@438.58,1000 378,1000 358.47,980.47 358.47,761.53 400,720 400,612.16 414.08,598.08 457.92,598.08 665,391 665,173 v1(713,125)
RCLK_ISO: TP27.1 U17.12 U18.6 | length 495.5
  Top Layer w8: U18.6@1004.49,125 TP27.1@1160,125 1160,150 1222,212 U17.12@1425.8,212 ; U17.12@1428.3,209.5 U17.12@1425.8,212 ; U17.12@1445.8,212 U17.12@1425.8,212
SCLK: J5.3 U15.4 | length 651.2
  Top Layer w8: v4(315,653) 390,653 625.5,417.5 U15.4@815.59,417.5
  Bottom Layer w8: J5.3@261.42,653.54 v4@314.46,653.54
SCLK_ISO: R42.2 TP20.1 U2.8 U5.8 U13.37 U17.11 | length 2712.7
  Top Layer w8: R42.2@1173.62,420 1470,420 TP20.1@1490,440 1616,566 1936,566 1947.52,577.52 U13.37@1947.52,626.22 1947.52,1422.52 2040,1515 2126.82,1515 2191.72,1579.9 2294.3,1579.9 U2.8@2295.7,1581.3 ; U17.11@1428.3,235.1 v1(1490,235.1) ; 1948.04,1090.52 2294.92,1090.52 U5.8@2295.7,1091.3
  Bottom Layer w8: v1(1490,235.1) TP20.1@1490,440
